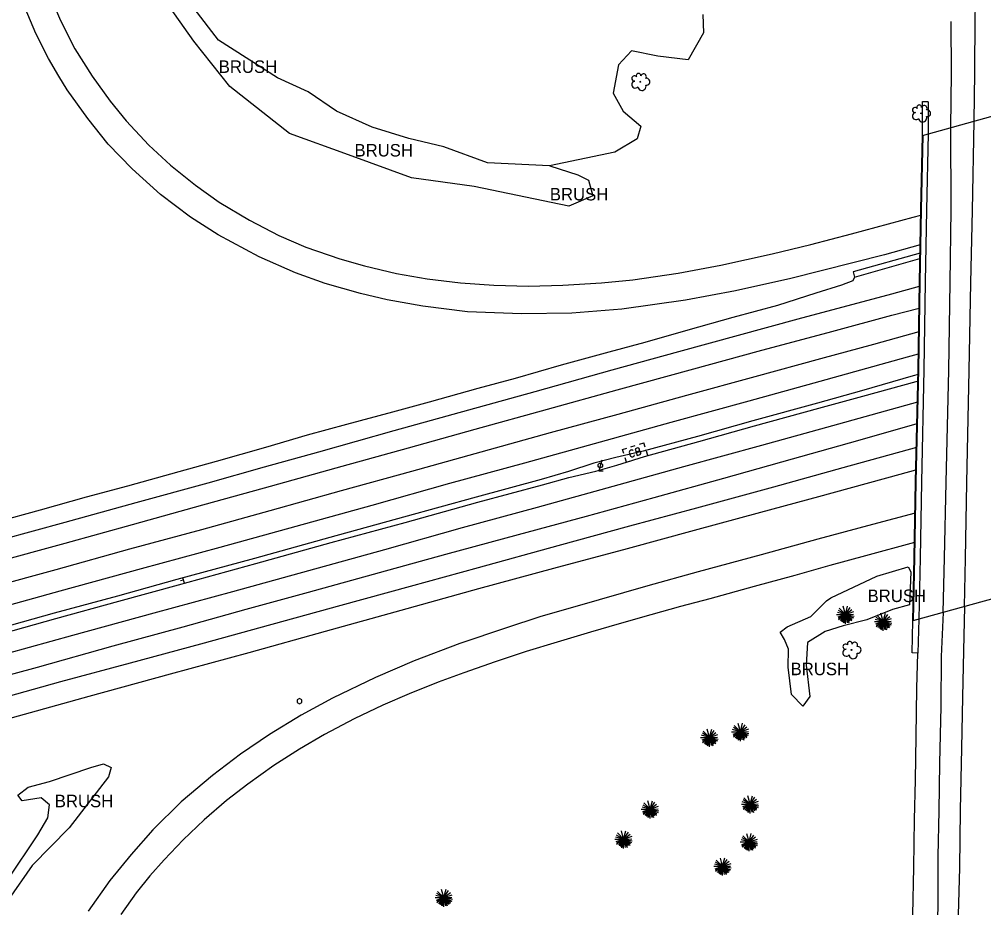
# Model space of a CAD drawing. Extents: x 2129547 to 2134906, y 657330 to 659734.
# Drawn here: x 2131944 to 2132485, y 658221 to 658719 of the extents above; entities that cross this region are included whole.
import ezdxf

# ---------------------------------------------------------------- set-up
doc = ezdxf.new("R2010")
doc.units = 0
for name, color, linetype in [('BR_X_SV_Deck_Top', 7, 'Continuous'), ('Default', 7, 'Continuous'), ('DR_X_Cells', 7, 'Continuous'), ('DT_X_Void', 7, 'Continuous'), ('LT_X_Poles', 7, 'Continuous'), ('PM_X_Edge_Line', 7, 'Continuous'), ('PM_X_Lane_Line', 7, 'Continuous'), ('PV_X_EOP2', 7, 'Continuous'), ('PV_X_Shoulder', 7, 'Continuous'), ('RD_X_Cells', 7, 'Continuous'), ('RD_X_Concrete_Barrier', 7, 'Continuous'), ('RD_X_Fence', 7, 'Continuous'), ('RD_X_Wall', 7, 'Continuous'), ('SN_X_Public', 7, 'Continuous'), ('VG_X_Cells', 7, 'Continuous'), ('VG_X_Shrub_Line_Lt', 7, 'Continuous'), ('VG_X_Text', 7, 'Continuous'), ('VG_X_Tree_Line_Lt', 7, 'Continuous')]:
    doc.layers.add(name, color=color, linetype=linetype)

# ---------------------------------------------------------------- blocks, each defined once
blk = doc.blocks.new('LPOLE')
at = {"layer": 'LT_X_Poles'}
blk.add_lwpolyline([(0.01, 0.0375), (-0.01, -0.0385), (0.02, -0.0385)], dxfattribs=at)
blk.add_circle((0, 0), 0.0165, dxfattribs=at)
blk = doc.blocks.new('POST')
at = {"layer": 'RD_X_Cells'}
blk.add_lwpolyline([(-0.0165, -0.0095), (0, -0.019), (0.0165, -0.0095), (0.0165, 0.0095), (0, 0.019), (-0.0165, 0.0095), (-0.0165, -0.0095)], dxfattribs=at)
blk = doc.blocks.new('SGN1P')
at = {"layer": 'SN_X_Public'}
for p, q in [((0, 0), (-0.02032, 0)), ((0, 0.02032), (0, -0.02032))]:
    blk.add_line(p, q, dxfattribs=at)
blk = doc.blocks.new('TREE')
at = {"layer": 'VG_X_Cells'}
blk.add_circle((0, 0), 0.00305, dxfattribs=at)
for centre, radius, start, end in [((-0.0362, -0.0197), 0.0251, 96.17219, 320.57371), ((-0.042, 0.0237), 0.0187, 39.06254, 279.54124), ((-0.0125, 0.0428), 0.0167, 354.0047, 205.97412), ((0.0232, 0.0359), 0.0197, 323.82996, 165.0376), ((0.0439, 0.0005), 0.0243, 259.14531, 101.45961), ((0.012, -0.0331), 0.029, 184.94757, 19.45715)]:
    blk.add_arc(centre, radius, start, end, dxfattribs=at)
blk = doc.blocks.new('ETREE')
at = {"layer": 'VG_X_Cells'}
for p, q in [((-0.0627, 0), (0, 0)), ((0, 0), (-0.056, 0.015)), ((0, 0), (-0.0545, -0.0198)), ((0, 0), (-0.0506, -0.029)), ((0, 0), (-0.0496, 0.0292)), ((0, 0), (-0.0496, -0.038)), ((0, 0), (-0.0443, 0.0443)), ((0, 0), (-0.0374, -0.044)), ((0, 0), (-0.0294, -0.051)), ((0, 0), (-0.0211, -0.0551)), ((0, 0), (-0.016, -0.0617)), ((0, 0), (-0.0157, 0.0586)), ((0, 0), (-0.0069, -0.0583)), ((0, 0), (0.016, 0.0597)), ((0, 0), (0.0337, 0.0493)), ((0, 0), (0.0464, 0.0356)), ((0, 0), (0.0602, 0.0204)), ((0, 0), (0.0573, 0.0012)), ((0, -0.0665), (0, 0)), ((0, 0), (0.0117, -0.0589)), ((0, 0), (0.0246, -0.0593)), ((0, 0), (0.0322, -0.0482)), ((0, 0), (0.0456, -0.0447)), ((0, 0), (0.0485, -0.0324)), ((0, 0), (0.0567, -0.0247)), ((0, 0), (0.0613, -0.0122))]:
    blk.add_line(p, q, dxfattribs=at)
blk = doc.blocks.new('POINT_DISPLAY')
at = {"layer": 'Default'}
blk.add_line((0, 0), (0, 0), dxfattribs=at)
blk = doc.blocks.new('GCB-X')
at = {"layer": 'Default'}
for p, q in [((-0.0317, 0.019), (-0.019, 0.019)), ((-0.0317, 0.0063), (-0.0317, 0.019)), ((-0.0063, 0.019), (0.0063, 0.019)), ((0.0034, 0.0007), (0.0124, 0.0007)), ((0.019, 0.019), (0.0317, 0.019)), ((0.0317, 0.0063), (0.0317, 0.019)), ((-0.0317, -0.019), (-0.0317, -0.0063)), ((-0.0317, -0.019), (-0.019, -0.019)), ((-0.0063, -0.019), (0.0063, -0.019)), ((0.019, -0.019), (0.0317, -0.019)), ((0.0317, -0.019), (0.0317, -0.0063))]:
    blk.add_line(p, q, dxfattribs=at)
blk.add_lwpolyline([(0.0116, 0.0099), (0.0034, 0.0099), (0.0034, -0.0104), (0.0124, -0.0104)], dxfattribs=at)
for centre, radius, start, end in [((0.0071, 0), 0.0233, 164.8107, 195.1893), ((-0.0094, 0.0037), 0.00645, 21.5603, 158.4397), ((0.0101, 0.0051), 0.00501, 296.8207, 73.0013), ((0.0101, -0.0049), 0.00597, 292.0547, 67.9453), ((-0.0094, -0.0037), 0.00645, 201.5603, 338.4397)]:
    blk.add_arc(centre, radius, start, end, dxfattribs=at)
for p in [(0, 0.019), (0, 0.019), (-0.0317, 0), (0, 0), (0, 0), (0, 0), (0, -0.019), (0, -0.019), (0.0317, 0)]:
    blk.add_blockref('POINT_DISPLAY', p, dxfattribs=at)

msp = doc.modelspace()

# ---------------------------------------------------------------- linework, layer by layer
at = {"layer": 'BR_X_SV_Deck_Top'}
msp.add_lwpolyline([(2132530.48, 658676.28), (2132529.61, 658630.47), (2132528.8, 658593.03), (2132527.85, 658548.59), (2132526.78, 658491.02), (2132525.63, 658436.44), (2132525.06, 658404.09), (2132445.09, 658382.12), (2132445.85, 658417.49), (2132446.61, 658459.94), (2132448.03, 658522.99), (2132448.8, 658571.92), (2132449.56, 658612.57), (2132450.41, 658654.1)], close=True, dxfattribs=at)
at = {"layer": 'DT_X_Void'}
msp.add_lwpolyline([(2132530.48, 658676.28), (2132529.61, 658630.47), (2132528.8, 658593.03), (2132527.85, 658548.59), (2132526.78, 658491.02), (2132525.63, 658436.44), (2132525.06, 658404.09), (2132445.09, 658382.12), (2132445.85, 658417.49), (2132446.61, 658459.94), (2132448.03, 658522.99), (2132448.8, 658571.92), (2132449.56, 658612.57), (2132450.41, 658654.1)], close=True, dxfattribs=at)
at = {"layer": 'PM_X_Edge_Line'}
for points in [[(2131960.9, 658734.03), (2131967.4, 658718.55), (2131975.48, 658702.8), (2131985.07, 658687.41), (2131995.18, 658673.43), (2132004.18, 658662.29), (2132016.83, 658648.79), (2132028.95, 658637.45), (2132042.99, 658626.23), (2132056.29, 658616.73), (2132073.25, 658606.62), (2132089.81, 658598.17), (2132104.94, 658591.6), (2132123.91, 658585), (2132137.74, 658580.99), (2132155.77, 658576.83), (2132172.82, 658573.76), (2132191.53, 658571.51), (2132210.27, 658570.15), (2132229.69, 658569.71), (2132248.87, 658570.18), (2132270.5, 658571.53), (2132288.08, 658573.31), (2132313.5, 658576.96), (2132337.39, 658581.46), (2132366.21, 658587.81), (2132387.88, 658593.05), (2132410.75, 658599.03), (2132445.33, 658608.31), (2132449.5, 658609.45)], [(2132449.19, 658592.85), (2132429.11, 658587.26), (2132376.71, 658573.91), (2132345.62, 658567.11), (2132317.62, 658561.88), (2132282.04, 658556.85), (2132253.93, 658554.56), (2132225.8, 658554.08), (2132195.49, 658555.36), (2132170.42, 658558.37), (2132150.48, 658562.05), (2132135.49, 658565.57), (2132115.8, 658571.26), (2132099.04, 658577.17), (2132078.78, 658586.2), (2132055.72, 658598.53), (2132040.3, 658608.28), (2132023.34, 658620.99), (2132007.56, 658635.39), (2131994.1, 658649.25), (2131982.68, 658663.59), (2131971.17, 658679.77), (2131966.47, 658687.39), (2131960.73, 658697.23), (2131953.58, 658711.22), (2131945.99, 658729.03)], [(2131934.57, 658427.57), (2131970.07, 658437.3), (2132009.75, 658448.37), (2132050.08, 658459.48), (2132081.65, 658468.35), (2132112.08, 658476.89), (2132154.4, 658488.77), (2132196.27, 658500.4), (2132233.32, 658510.67), (2132276.49, 658522.77), (2132313.9, 658533), (2132380.86, 658551.33), (2132433.36, 658565.44), (2132448.76, 658569.62)], [(2131930.76, 658388.75), (2131967.21, 658398.86), (2132012.86, 658411.34), (2132056.82, 658423.38), (2132099.51, 658435.2), (2132141.98, 658446.96), (2132185.63, 658459.18), (2132227.56, 658470.57), (2132270.01, 658482.48), (2132309.6, 658493.41), (2132353.27, 658505.47), (2132393.11, 658516.45), (2132442.06, 658529.97), (2132448.17, 658531.65)], [(2132447.62, 658504.56), (2132400.01, 658491.42), (2132360.17, 658480.44), (2132316.54, 658468.34), (2132276.97, 658457.37), (2132234.48, 658445.54), (2132192.54, 658434.15), (2132148.94, 658421.94), (2132106.44, 658410.17), (2132063.72, 658398.35), (2132019.72, 658386.3), (2131974.1, 658373.83), (2131937.71, 658363.73)], [(2131911.33, 658319.88), (2131947.12, 658329.81), (2131983.45, 658339.89), (2132029.02, 658352.35), (2132073.06, 658364.41), (2132115.84, 658376.25), (2132158.38, 658388.03), (2132201.89, 658400.21), (2132243.81, 658411.6), (2132285.14, 658422.66), (2132322.67, 658432.93), (2132359.91, 658442.98), (2132392.39, 658451.82), (2132437.91, 658464.23), (2132446.76, 658466.67)], [(2132446.3, 658442.44), (2132422.38, 658436.01), (2132391.81, 658427.78), (2132360.11, 658419.09), (2132324.75, 658409.52), (2132296.55, 658401.66), (2132269.23, 658393.93), (2132235.94, 658384.32), (2132217.27, 658378.17), (2132191.19, 658369.37), (2132165.65, 658359.71), (2132143.84, 658350.37), (2132119.77, 658338.7), (2132102.26, 658329.16), (2132084.59, 658318.34), (2132068.25, 658307.38), (2132052.55, 658295.39), (2132035.09, 658280.57), (2132019.04, 658264.91), (2132006.91, 658251.17), (2131995.03, 658236.44), (2131982.9, 658219.25)], [(2132446.01, 658426.05), (2132418.55, 658418.45), (2132398.61, 658413.11), (2132378.97, 658407.57), (2132356.22, 658401.32), (2132331.32, 658394.48), (2132314.87, 658390.07), (2132298.29, 658385.42), (2132280.46, 658380.45), (2132264.42, 658375.78), (2132245.72, 658370.19), (2132228.37, 658364.83), (2132211.01, 658359.13), (2132193.33, 658352.92), (2132179.05, 658347.66), (2132162.78, 658341.07), (2132148.1, 658334.71), (2132132.04, 658327.07), (2132115.25, 658318.26), (2132101.23, 658310.05), (2132086.89, 658300.9), (2132072.37, 658290.48), (2132060.48, 658281.34), (2132047.92, 658270.51), (2132036.1, 658259.35), (2132025.45, 658248.15), (2132017.46, 658239.04), (2132009.76, 658229.5), (2132001.1, 658217.44)], [(2132445.07, 658217.17), (2132445.56, 658243.86), (2132446.07, 658270.71), (2132446.54, 658292.78), (2132446.89, 658317.25), (2132447.37, 658344.31), (2132447.94, 658364.01)]]:
    msp.add_lwpolyline(points, dxfattribs=at)
at = {"layer": 'PM_X_Lane_Line'}
for points in [[(2132479.46, 658662.15), (2132479.91, 658689.3), (2132480.02, 658720.13), (2132480.79, 658745.78), (2132481.72, 658774.42), (2132481.81, 658805.92), (2132482.47, 658839.62), (2132482.81, 658868.33), (2132483.47, 658896.67), (2132483.79, 658929.03), (2132484.16, 658961.85), (2132485.12, 658987.76), (2132486.03, 659018.91)], [(2132466.41, 658658.54), (2132466.75, 658689.05), (2132466.46, 658718)], [(2132474.04, 658390.07), (2132474.57, 658416.92), (2132475.39, 658459.36), (2132476.62, 658522.45), (2132477.6, 658571.47), (2132478.43, 658612.15), (2132479.49, 658662.15)], [(2132462.01, 658386.77), (2132462.84, 658417.32), (2132463.74, 658459.67), (2132465.29, 658522.66), (2132466.08, 658571.68), (2132466.58, 658612.43), (2132466.42, 658658.54)], [(2131929.53, 658414.52), (2131970.06, 658425.59), (2132007.7, 658436.03), (2132047.17, 658447.11), (2132081.74, 658456.54), (2132125.15, 658468.71), (2132162.35, 658478.99), (2132199.86, 658489.6), (2132240.31, 658500.73), (2132279.28, 658511.57), (2132322.3, 658523.39), (2132358.44, 658533.16), (2132399.66, 658544.29), (2132433.33, 658553.43), (2132448.57, 658557.39)], [(2132448.36, 658544.02), (2132422.98, 658537.04), (2132393.23, 658528.96), (2132356.55, 658518.93), (2132318.16, 658508.3), (2132279.68, 658497.81), (2132241.89, 658487.5), (2132199.64, 658475.71), (2132164.03, 658465.79), (2132124.7, 658454.85), (2132084.62, 658443.67), (2132046.45, 658433.09), (2132006.06, 658422.23), (2131964.81, 658410.75), (2131928.35, 658400.84)], [(2132447.34, 658492.47), (2132414.04, 658483.03), (2132377.35, 658472.66), (2132338.98, 658461.94), (2132299.97, 658451.09), (2132261.92, 658440.57), (2132223.86, 658430.2), (2132183.07, 658419.17), (2132146.06, 658409.06), (2132106.18, 658398.02), (2132071.24, 658388.38), (2132035.93, 658378.59), (2131996.67, 658367.82), (2131954.3, 658356), (2131919.03, 658346.33)], [(2132447.04, 658479.23), (2132405.78, 658467.83), (2132366.97, 658457.08), (2132323.81, 658445.26), (2132286.34, 658435.06), (2132246.1, 658424.06), (2132201.54, 658411.79), (2132163.43, 658401.26), (2132124.58, 658390.65), (2132085.74, 658379.96), (2132045.82, 658368.96), (2132006.46, 658358.33), (2131967.36, 658347.8), (2131931.86, 658338.02)], [(2132474.02, 658390.07), (2132473.42, 658365.27), (2132472.95, 658339.28), (2132472.3, 658310.66), (2132471.69, 658275.89), (2132471.2, 658243.55), (2132470.4, 658217.28), (2132469.98, 658193.11), (2132469.23, 658155.06), (2132468.6, 658121.03), (2132467.94, 658090.01), (2132467.68, 658065.42), (2132467.2, 658037.93), (2132466.53, 658012.04), (2132466.4, 657983.84), (2132465.94, 657956.69), (2132465.45, 657928.79), (2132463.63, 657894.51)], [(2132462, 658386.77), (2132461, 658362.01), (2132460.74, 658334.08), (2132460.05, 658302.31), (2132459.55, 658275.55), (2132459.17, 658250.08), (2132458.99, 658223.44), (2132458.44, 658196.89), (2132457.62, 658167.15), (2132456.82, 658133.76), (2132456.35, 658102.44), (2132455.51, 658067.44), (2132455.12, 658037.58), (2132454.94, 658008.45), (2132454.34, 657977.62), (2132453.42, 657949.61), (2132453.06, 657922.55), (2132452.09, 657894.93)]]:
    msp.add_lwpolyline(points, dxfattribs=at)
at = {"layer": 'PV_X_EOP2'}
for points in [[(2131934.57, 658427.57), (2131970.07, 658437.3), (2132009.75, 658448.37), (2132050.08, 658459.48), (2132081.65, 658468.35), (2132112.08, 658476.89), (2132154.4, 658488.77), (2132196.27, 658500.4), (2132233.32, 658510.67), (2132276.49, 658522.77), (2132313.9, 658533), (2132380.86, 658551.33), (2132433.36, 658565.44), (2132448.76, 658569.62)], [(2131930.76, 658388.75), (2131967.21, 658398.86), (2132012.86, 658411.34), (2132056.82, 658423.38), (2132099.51, 658435.2), (2132141.98, 658446.96), (2132185.63, 658459.18), (2132227.56, 658470.57), (2132270.01, 658482.48), (2132309.6, 658493.41), (2132353.27, 658505.47), (2132393.11, 658516.45), (2132442.06, 658529.97), (2132448.17, 658531.65)], [(2132447.62, 658504.56), (2132400.01, 658491.42), (2132360.17, 658480.44), (2132316.54, 658468.34), (2132276.97, 658457.37), (2132234.48, 658445.54), (2132192.54, 658434.15), (2132148.94, 658421.94), (2132106.44, 658410.17), (2132063.72, 658398.35), (2132019.72, 658386.3), (2131974.1, 658373.83), (2131937.71, 658363.73)], [(2131911.33, 658319.88), (2131947.12, 658329.81), (2131983.45, 658339.89), (2132029.02, 658352.35), (2132073.06, 658364.41), (2132115.84, 658376.25), (2132158.38, 658388.03), (2132201.89, 658400.21), (2132243.81, 658411.6), (2132285.14, 658422.66), (2132322.67, 658432.93), (2132359.91, 658442.98), (2132392.39, 658451.82), (2132437.91, 658464.23), (2132446.76, 658466.67)]]:
    msp.add_lwpolyline(points, dxfattribs=at)
at = {"layer": 'PV_X_Shoulder'}
msp.add_lwpolyline([(2132412.39, 658574.77), (2132411.53, 658572.62), (2132405.05, 658570.22), (2132390.71, 658565.67), (2132369.22, 658558.9), (2132344.11, 658552.16), (2132318.88, 658545.04), (2132294.86, 658538.17), (2132274.74, 658532.61), (2132247.97, 658525.36), (2132222.12, 658517.99), (2132201.22, 658512.34), (2132173.93, 658504.66), (2132153.36, 658499.13), (2132127.61, 658492.16), (2132105.6, 658486.13), (2132082.33, 658479.31), (2132054.65, 658471.47), (2132033.71, 658465.59), (2132004.94, 658457.48), (2131981.82, 658451.33), (2131955.96, 658444.11), (2131931.29, 658437.47)], dxfattribs=at)
at = {"layer": 'RD_X_Concrete_Barrier'}
for points in [[(2132449.1, 658588.25), (2132411.57, 658577.65), (2132412.39, 658574.77), (2132449.04, 658585.12)], [(2132447.97, 658520.12), (2132445.19, 658519.36), (2132416.21, 658510.96), (2132391.66, 658504.16), (2132355.44, 658494.2), (2132324.33, 658485.43), (2132293.95, 658477.13), (2132278.54, 658473.64), (2132266.24, 658470.43), (2132252.03, 658465.82), (2132236.77, 658461.28), (2132200.41, 658451.4), (2132159.66, 658440.1), (2132118.36, 658428.78), (2132076.02, 658417.08), (2132032.64, 658405.22), (2131999.26, 658395.98), (2131963.88, 658386.29), (2131927.86, 658376.2)], [(2131928.66, 658373.31), (2131964.68, 658383.4), (2132000.05, 658393.09), (2132033.44, 658402.33), (2132076.82, 658414.18), (2132119.16, 658425.89), (2132160.46, 658437.21), (2132201.21, 658448.5), (2132237.59, 658458.4), (2132252.29, 658462.35), (2132267.46, 658465.9), (2132279.25, 658469.31), (2132294.68, 658474.22), (2132325.13, 658482.54), (2132356.24, 658491.31), (2132392.46, 658501.27), (2132417.02, 658508.08), (2132446.87, 658516.14), (2132447.88, 658516.42)]]:
    msp.add_lwpolyline(points, dxfattribs=at)
at = {"layer": 'RD_X_Fence'}
msp.add_lwpolyline([(2132445.49, 658382.23), (2132446.25, 658417.48), (2132447.01, 658459.94), (2132448.43, 658522.98), (2132449.2, 658571.92), (2132449.96, 658612.56), (2132450.81, 658654.21)], dxfattribs=at)
at = {"layer": 'RD_X_Wall'}
msp.add_lwpolyline([(2132450.41, 658654.1), (2132450.49, 658673.12), (2132453.24, 658673.11), (2132453.74, 658673.1), (2132453.68, 658655.01), (2132452.81, 658612.5), (2132452.05, 658571.87), (2132451.28, 658522.93), (2132449.86, 658459.88), (2132449.1, 658417.43), (2132448.43, 658383.04), (2132447.94, 658364.01), (2132447.44, 658364.03), (2132444.7, 658364.1), (2132445.09, 658382.12)], dxfattribs=at)
at = {"layer": 'VG_X_Shrub_Line_Lt'}
msp.add_lwpolyline([(2132241.57, 658637.13), (2132257.23, 658632.16), (2132263.35, 658629.08), (2132265.8, 658620.39), (2132252.28, 658614.57), (2132199.28, 658625.58), (2132164.16, 658630.46), (2132128.73, 658643.29), (2132095.7, 658655.21), (2132062.3, 658681.54), (2132042.01, 658707.06), (2132015.09, 658745.42), (2131999.97, 658777.1), (2131997.64, 658790.64), (2132002.68, 658798.92)], dxfattribs=at)
for points in [[(2132399.02, 658394.89), (2132424.96, 658407.12), (2132442.42, 658412.39), (2132444.01, 658409.55), (2132443.15, 658391.08), (2132433.61, 658388.47), (2132419.25, 658382.68), (2132406.11, 658379.32), (2132395.9, 658376.08), (2132386.09, 658369.86), (2132385.22, 658357.27), (2132387.38, 658339.56), (2132383.39, 658334.2), (2132377.03, 658340.7), (2132375.23, 658356.09), (2132375.39, 658366.22), (2132373.22, 658371.59), (2132370.73, 658375.73), (2132374.57, 658378.75), (2132387.96, 658384.55), (2132396.7, 658393.27)], [(2131961.21, 658292.01), (2131984.37, 658299.77), (2131991.4, 658301.91), (2131995.69, 658299.87), (2131994.31, 658294.6), (2131972.25, 658266.05), (2131951.44, 658244.87), (2131938.22, 658225.9), (2131934.72, 658229.51), (2131937.63, 658236.68), (2131954.69, 658262.06), (2131960.23, 658271.58), (2131961.12, 658278.9), (2131956.58, 658282.83), (2131945.9, 658281.11), (2131943.43, 658284.3), (2131949.29, 658288.76)]]:
    msp.add_lwpolyline(points, close=True, dxfattribs=at)
at = {"layer": 'VG_X_Tree_Line_Lt'}
msp.add_lwpolyline([(2132327.28, 658721.96), (2132327.82, 658711.7), (2132319.18, 658696.53), (2132302.2, 658698.57), (2132287.42, 658701.52), (2132280.16, 658693.75), (2132277.05, 658677.95), (2132282.77, 658667.69), (2132292.61, 658659.43), (2132290.59, 658652.24), (2132277.96, 658644.76), (2132241.42, 658637.09), (2132206.78, 658638.78), (2132182.19, 658647.87), (2132162.52, 658652.49), (2132142.04, 658658.75), (2132122.07, 658667.86), (2132106.11, 658678.65), (2132088.92, 658686.48), (2132055.99, 658707.55), (2132042.26, 658725.35)], dxfattribs=at)

# ---------------------------------------------------------------- block references
at = {"layer": 'DR_X_Cells', "xscale": 196.85, "yscale": 196.85000000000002, "rotation": 17.222694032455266}
msp.add_blockref('GCB-X', (2132289.4, 658476.46), dxfattribs=at)
at = {"layer": 'LT_X_Poles', "xscale": 78.74000000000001, "yscale": 78.74000000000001}
msp.add_blockref('LPOLE', (2132269.93, 658469.19), dxfattribs=at)
at = {"layer": 'RD_X_Cells', "xscale": 78.74000000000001, "yscale": 78.74000000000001}
msp.add_blockref('POST', (2132101.32, 658336.95), dxfattribs=at)
at = {"layer": 'SN_X_Public', "xscale": 78.74, "yscale": 78.74000000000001, "rotation": 16.775595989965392}
msp.add_blockref('SGN1P', (2132036.24, 658404.92), dxfattribs=at)
at = {"layer": 'VG_X_Cells', "xscale": 78.74000000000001, "yscale": 78.74000000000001}
for name, p in [('TREE', (2132292.34, 658684.26)), ('TREE', (2132449.64, 658666.56)), ('ETREE', (2132407.27, 658385.63)), ('ETREE', (2132428.46, 658381.71)), ('TREE', (2132410.69, 658365.74)), ('ETREE', (2132348.4, 658319.92)), ('ETREE', (2132331.08, 658316.73)), ('ETREE', (2132297.82, 658276.51)), ('ETREE', (2132353.89, 658279.36)), ('ETREE', (2132282.98, 658259.71)), ('ETREE', (2132353.29, 658258.1)), ('ETREE', (2132338.42, 658244.48)), ('ETREE', (2132182.23, 658226.94))]:
    msp.add_blockref(name, p, dxfattribs=at)

# ---------------------------------------------------------------- texts
at = {"layer": 'VG_X_Shrub_Line_Lt'}
msp.add_text('BRUSH', height=7, dxfattribs=at).set_placement((2131964.16, 658277.58))
at = {"layer": 'VG_X_Text'}
for p in [(2132056.06, 658689.23), (2132132.15, 658642.36), (2132241.63, 658617.73), (2132419.71, 658392.59), (2132376.57, 658351.6)]:
    msp.add_text('BRUSH', height=7, dxfattribs=at).set_placement(p)

doc.saveas('drawing.dxf')
